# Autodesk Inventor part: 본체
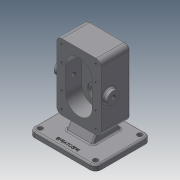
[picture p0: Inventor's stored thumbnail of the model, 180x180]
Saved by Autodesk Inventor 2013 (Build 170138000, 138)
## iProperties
Created: 2020-04
Part Number: 본체
Material: Generic
Document SubType Name: Modeling
Designer: user
Density: 1 g/cm^3
Author: user
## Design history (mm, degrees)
sketch "스케치1"
  geometry: L1 (40, 60)-(-40, 60); L2 (-40, 60)-(-40, -60); L3 (-40, -60)-(40, -60); L4 (40, -60)-(40, 60); L5 (40, 60)-(-40, -60); L6 (-40, 60)-(40, -60); 1 further point
  constraints: 12 end point, 2 midpoint, 2 parallel, 1 horizontal, 1 perpendicular
  dimensions: "d0" = 80 distance of L3.end L2.end; "d1" = 120 distance of L2.end L1.end
extrude "돌출1" new body sketch "스케치1" stored distance "d2" = 53; taper "d3" = 0 deg
fillet "모깎기1" dims "d4" = 9
sketch "스케치2"
  geometry: A1 r 9 centre (-31, -51) between (-40, -51) and (-31, -60) reference; A2 r 9 centre (31, -51) between (31, -60) and (40, -51) reference; A3 r 9 centre (31, 51) between (40, 51) and (31, 60) reference; A4 r 9 centre (-31, 51) between (-31, 60) and (-40, 51) reference; 5 further points
  constraints: 4 coincident
hole "구멍1" sketch "스케치2" at (-31, 51), (31, 51), (31, -51), (-31, -51) diameter "d5" = 4.134; stored, may be unused: countersink angle "d9" = 90 deg, drill point angle "d11" = 118 deg; dims "d6" = 10, "d7" = 4, "d8" = 2, "d10" = 12
sketch "스케치3"
  geometry: L1 (-40, 51)-(-40, -51) reference; L2 (-31, 51)-(-31, 22); L3 (-31, 22)-(-31, -22); A1 r 9 centre (-31, 51) between (-31, 60) and (-40, 51) reference; 3 further points
  constraints: 4 end point, 2 coincident, 1 collinear, 1 parallel
  dimensions: "d12" = 29 distance of L2.start L2.end; "d13" = 44 distance of L2.end L3.end
hole "구멍2" sketch "스케치3" at (-31, 22), (-31, -22) diameter "d14" = 4.134; stored, may be unused: countersink angle "d18" = 90 deg, drill point angle "d20" = 118 deg; dims "d15" = 10, "d16" = 4, "d17" = 2, "d19" = 12
sketch "스케치4"
  geometry: L1 (-24, 22)-(24, 22); L2 (24, 22)-(24, -22); L3 (24, -22)-(-24, -22); L4 (-24, -22)-(-24, 22); L5 (-24, 22)-(24, -22); L6 (24, 22)-(-24, -22); C1 r 24 at (0, 22); C2 r 24 at (0, -22); 1 further point
  constraints: 12 end point, 4 midpoint, 2 centre point, 2 parallel, 1 horizontal, 1 perpendicular
  dimensions: "d21" = 48 distance of L2.end L3.end; "d22" = 44 distance of L1.end L2.end; "d23" = 48 diameter of C1; "d24" = 48 diameter of C2
extrude "돌출2" cut sketch "스케치4" distance "d25" = 29; taper "d26" = 0 deg
sketch "스케치5"
  geometry: L1 (-31, -60)-(31, -60) reference; L2 (0, 0)-(0, 22); C1 r 19 at (0, 22)
  constraints: 2 end point, 1 centre point, 1 coincident, 1 perpendicular
  dimensions: "d27" = 22 distance of L2.start L2.end; "d28" = 38 diameter of C1
extrude "돌출3" join sketch "스케치5" distance "d29" = 17; taper "d30" = 0 deg
sketch "스케치6"
  geometry: A1 r 24 centre (0, 22) between (24, 22) and (-24, 22) reference; 2 further points
  constraints: 1 coincident
hole "구멍3" sketch "스케치6" at (0, 22) diameter "d31" = 17; stored, may be unused: countersink angle "d35" = 90 deg, drill point angle "d37" = 118 deg; dims "d32" = 10, "d33" = 25, "d34" = 15, "d36" = 12
sketch "스케치7"
  geometry: C1 r 12.5 at (0, -22); A1 r 24 centre (0, -22) between (-24, -22) and (24, -22) reference; 1 further point
  constraints: 1 centre point, 1 coincident
  dimensions: "d38" = 25 diameter of C1
extrude "돌출4" cut sketch "스케치7" distance "d39" = 15; taper "d40" = 0 deg
sketch "스케치8"
  geometry: C1 r 8.5 at (0, 0) reference; C2 r 19 at (0, 0) reference; C3 r 14 at (0, 0); 1 further point
  constraints: 1 centre point, 1 coincident
  dimensions: "d41" = 28 diameter of C3
extrude "돌출5" cut sketch "스케치8" distance "d42" = 7.3; taper "d43" = 0 deg
sketch "스케치9"
  geometry: L1 (-53, 0)-(-53, 102) reference; L2 (-53, 51)-(-39, 51); C1 r 11 at (-39, 51); 1 further point
  constraints: 2 end point, 1 centre point, 1 coincident, 1 midpoint, 1 perpendicular
  dimensions: "d44" = 14 distance of L2.start L2.end; "d45" = 22 diameter of C1
extrude "돌출6" join sketch "스케치9" distance "d46" = 8; taper "d47" = 0 deg
sketch "스케치10"
  geometry: C1 r 11 at (0, 0) reference; 2 further points
  constraints: 1 coincident
hole "구멍4" sketch "스케치10" at (0, 0) diameter "d48" = 8.376; stored, may be unused: countersink angle "d52" = 90 deg, drill point angle "d54" = 118 deg; dims "d49" = 10, "d50" = 25, "d51" = 15, "d53" = 12
chamfer "모따기1" distance "d55" = 1; stored, may be unused: second distance "d56" = 2, angle "d57" = 45 deg
chamfer "모따기2" distance "d58" = 0.7; stored, may be unused: second distance "d59" = 2, angle "d60" = 30 deg
fillet "모깎기2" dims "d61" = 0.5
fillet "모깎기3" dims "d62" = 3
fillet "모깎기4" dims "d63" = 3
fillet "모깎기5" dims "d64" = 3
node "작업 평면1"
sketch "스케치11"
  geometry: L1 (-31, -26.5)-(31, -26.5) reference; L2 (60, 56.5)-(-60, 56.5); L3 (-60, 56.5)-(-60, -43.5); L4 (-60, -43.5)-(60, -43.5); L5 (60, -43.5)-(60, 56.5); 2 further points
  constraints: 8 end point, 2 parallel, 1 horizontal, 1 midpoint, 1 perpendicular, 1 vertical alignment
  dimensions: "d66" = 120 distance of L4.end L3.end; "d67" = 100 distance of L3.end L2.end; "d68" = 83 distance between parallel lines of L2 L1
extrude "돌출7" join sketch "스케치11" distance "d69" = 10; taper "d70" = 0 deg
fillet "모깎기6" dims "d71" = 10
fillet "모깎기7" dims "d72" = 10
sketch "스케치12"
  geometry: C1 r 4.5 at (-50, 33.5); C2 r 4.5 at (50, 33.5); C3 r 4.5 at (-50, -46.5); C4 r 4.5 at (50, -46.5); A1 r 10 centre (-50, 33.5) between (-50, 43.5) and (-60, 33.5) reference; A2 r 10 centre (-50, -46.5) between (-60, -46.5) and (-50, -56.5) reference; A3 r 10 centre (50, -46.5) between (50, -56.5) and (60, -46.5) reference; A4 r 10 centre (50, 33.5) between (60, 33.5) and (50, 43.5) reference; 1 further point
  constraints: 4 centre point, 4 coincident
  dimensions: "d73" = 9 diameter of C1; "d74" = 9 diameter of C2; "d75" = 9 diameter of C3; "d76" = 9 diameter of C4
extrude "돌출8" cut sketch "스케치12" stored distance "d77" = 10; taper "d78" = 0 deg
sketch "스케치13"
  geometry: L1 (-60, -23.5)-(-60, 26.5) reference; L2 (51, -26.5)-(-51, -26.5) reference; L3 (-51, -26.5)-(-57, -26.5) reference; L4 (-80, -33.5)-(-80, 46.5) reference; L5 (-80, 51)-(-80, 42) reference; L6 (-80, -29)-(-80, -38) reference; L7 (-80, -33.5)-(-80, -43.5) reference; L8 (-80, 56.5)-(-80, 46.5) reference; L9 (-80, -43.5)-(-90, -43.5) reference; L10 (-80, -43.5)-(-80, -26.5); L11 (-80, -26.5)-(-60, -14.953); L12 (-60, 14.953)-(-80, 26.5); A1 r 3 centre (-57, -23.5) between (-60, -23.5) and (-57, -26.5) reference; 1 further point
  constraints: 6 end point, 4 point on line
  dimensions: "d79" = 17 distance of L7.end L10.end; "d80" = 60 deg angle of L4 L11; "d81" = 53 distance of L10.end L12.end; "d82" = 60 deg angle of L4 L12
extrude "돌출9" join sketch "스케치13" stored distance "d83" = 48; taper "d84" = 0 deg
fillet "모깎기8" dims "d85" = 3
fillet "모깎기9" dims "d86" = 3
fillet "모깎기10" dims "d87" = 3
sketch "스케치14"
  geometry: L1 (-60, 33.5)-(-60, -46.5) reference; L2 (-50, -56.5)-(50, -56.5) reference; 2 further points
  constraints: 1 other
  dimensions: "d88" = 60 distance from line of L1 point (0, -46.5); "d89" = 10 distance from line of L2 point (0, -46.5)
feature "엠보싱1" sketch "스케치14" dims "d0" = 80, "d1" = 120, "d90" = 0.5, "d91" = 0
node "솔리드1"
mirror "대칭1"
mirror "대칭2"
